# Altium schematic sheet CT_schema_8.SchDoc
size 258 x 245 mm
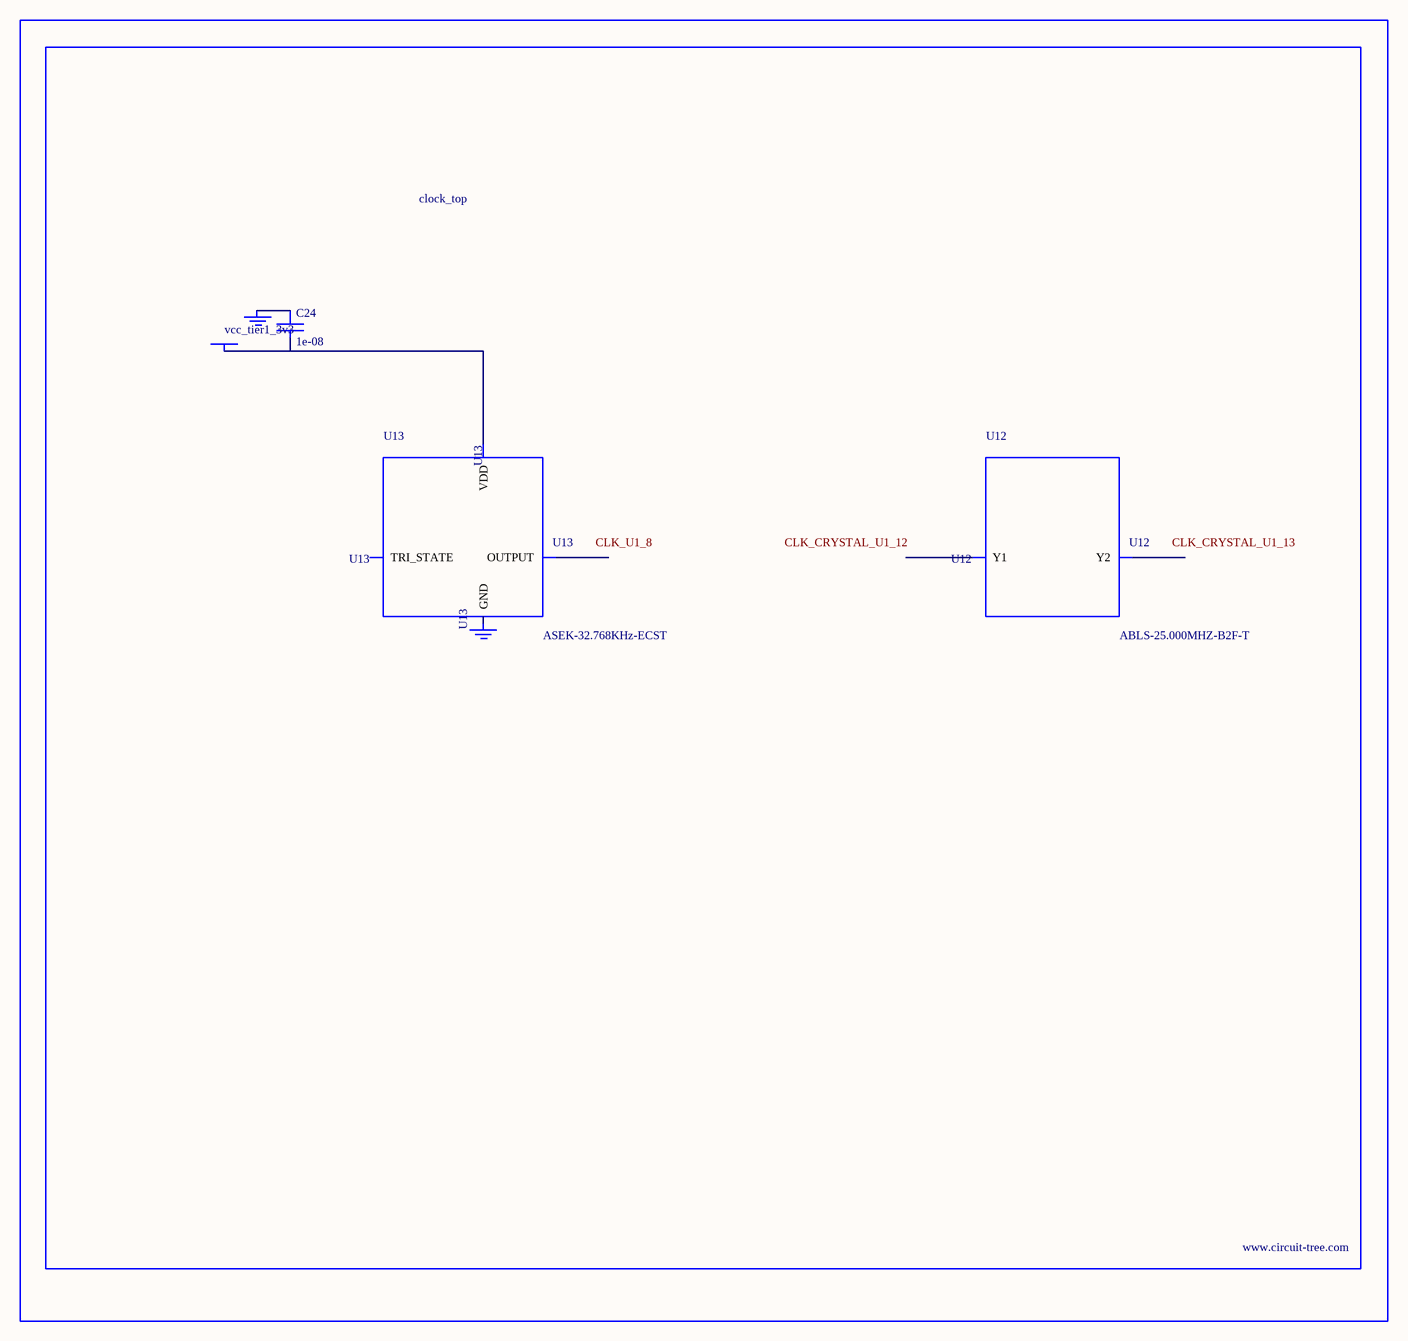
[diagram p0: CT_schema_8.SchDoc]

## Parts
BORDER7  (no value)
C24  1e-08  [C0402]
GND_INSTANCE_7_0  (no value)
GND_INSTANCE_7_1  (no value)
POWER_INSTANCE_7_0  vcc_tier1_3v3
U12  ABLS-25.000MHZ-B2F-T  [ABLS-25.000MHZ-B2F-T]
U13  ASEK-32.768KHz-ECST  [ASEK]

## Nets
NetC24_1: C24.1 GND_INSTANCE_7_0.0(GND)
NetC24_2: C24.2 POWER_INSTANCE_7_0.0(PWR) U13.4(VDD)

Not connected (* = marked no-connect by the designer): GND_INSTANCE_7_1 0(GND); U12 1(Y1) 2(Y2); U13 1(TRI_STATE) 2(GND) 3(OUTPUT)

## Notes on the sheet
- Labels drawn without touching a wire or pin: CLK_CRYSTAL_U1_12, CLK_CRYSTAL_U1_13, CLK_U1_8

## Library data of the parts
BORDER7 = BORDER_PAGE7
C24 = C0402C103K3RAC
GND_INSTANCE_7_0 GND_INSTANCE_7_1 = GND
POWER_INSTANCE_7_0 = PWR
